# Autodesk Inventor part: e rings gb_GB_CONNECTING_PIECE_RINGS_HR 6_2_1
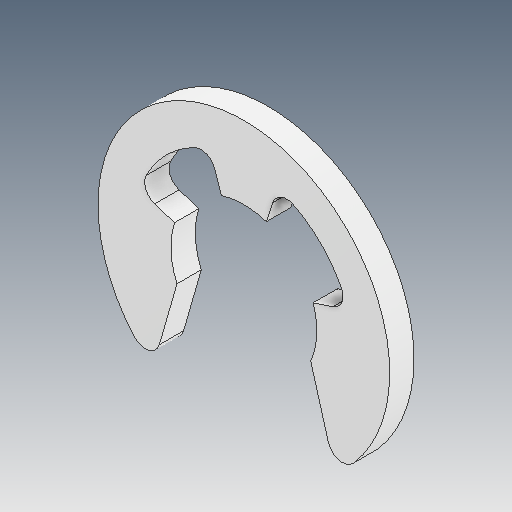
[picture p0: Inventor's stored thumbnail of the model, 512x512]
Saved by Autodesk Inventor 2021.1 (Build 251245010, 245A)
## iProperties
Created: 2021-05
Part Number: e rings gb_GB_CONNECTING_PIECE_RINGS_HR 6_2_1
Material: Ogólny
Document SubType Name: Modeling
Designer: user
Density: 1 g/cm^3
Appearance: Domyślna
Author: user
Revision Number: ÈÎºÎ
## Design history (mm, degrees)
feature "ÊäÈë1"
node "Bryła1"
